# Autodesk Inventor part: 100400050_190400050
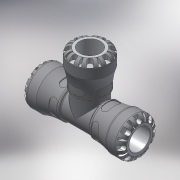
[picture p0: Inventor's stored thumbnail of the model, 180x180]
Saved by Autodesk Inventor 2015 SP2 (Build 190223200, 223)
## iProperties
Created: 2016-12
Part Number: 100400050_190400050
Material: Generic
Description: PLASSON TEE 50X50X50 SERIES 1
Document SubType Name: Modeling
Designer: KIM
Mass: 664.223 g
Surface Area: 733.008 cm^2
Volume: 474.445 cm^3
Density: 1 g/cm^3
Appearance: Default
Author: KIM
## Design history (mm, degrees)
derived "1004.ipt"
feature "Solid1::1004.ipt"
tag "TaggingFeature1"
body "Solid1"
other parameters: "d9" = 11.25, "d11" = 85, "d12" = 62.5, "d230" = 85, "d231" = 62.5, "d232" = 11.25, "d1" = 32.76, "d3" = 62.5, "d4" = 85, "d8" = 72.25, "d13" = 9, "d14" = 9, "d15" = 0, "d17" = 360 deg, "d19" = 8 deg, "d20" = 1, "d21" = 1, "d22" = 8 deg, "d24" = 0, "d26" = 360 deg, "d33" = 8.5, "d43" = 66.3, "d51" = 0.85, "d54" = 17.5, "d55" = 11, "d57" = 17.64, "d58" = 0, "d74" = 0, "d77" = 4.16667, "d78" = 78, "d79" = 66.3, "d80" = 214, "d82" = 1, "d115" = 360 deg, "d139" = 9, "d140" = 0, "d142" = 360 deg, "d207" = 90 deg, "d209" = 32.76, "d211" = 62.5, "d212" = 85, "d213" = 72.25, "d215" = 66.3, "d216" = 4.16667, "d217" = 78, "d225" = 124, "d226" = 78, "d228" = 14.875, "d229" = 9, "d233" = 9, "d234" = 0, "d236" = 360 deg, "d238" = 8 deg, "d239" = 8 deg, "d240" = 1, "d241" = 1, "d243" = 0, "d245" = 360 deg, "d247" = 1.7, "d248" = 4.68, "d249" = 4.68, "d250" = 14.875, "d252" = 17.5, "d253" = 11.5, "d254" = 17.64, "d255" = 0, "d257" = 360 deg, "d259" = 1, "d261" = 0, "d262" = 1.7, "d264" = 0, "d266" = 0, "d267" = 0.85, "E_" = 85, "l_" = 78, "A_" = 124, "H_" = 214
